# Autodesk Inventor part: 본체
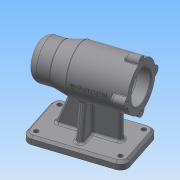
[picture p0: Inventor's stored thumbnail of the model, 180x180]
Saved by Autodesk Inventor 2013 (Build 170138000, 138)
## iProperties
Created: 2019-07
Part Number: 본체
Material: 알루미늄 6061
Document SubType Name: Modeling
Designer: Administrator
Density: 2.71 g/cm^3
Mass: 645.344 g
Surface Area: 653.867 cm^2
Volume: 238.134 cm^3
Author: Administrator
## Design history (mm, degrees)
sketch "스케치1"
  geometry: L1 (-56, 35)-(56, 35); L2 (56, 35)-(56, -35); L3 (56, -35)-(-56, -35); L4 (-56, -35)-(-56, 35); L5 (-56, 35)-(56, -35); L6 (56, 35)-(-56, -35); 1 further point
  constraints: 12 end point, 2 midpoint, 2 parallel, 1 horizontal, 1 perpendicular
  dimensions: "d0" = 112 distance of L2.end L3.end; "d1" = 70 distance of L1.end L2.end
extrude "돌출1" new body sketch "스케치1" distance "d2" = 10; taper "d3" = 0 deg
sketch "스케치2"
  geometry: L1 (-56, 80)-(-56, 105); L2 (-56, 105)-(-31, 105); L3 (-31, 105)-(-11, 110); L4 (-11, 110)-(56, 110); L5 (56, 110)-(56, 80); L6 (56, 80)-(-56, 80); L7 (-56, 0)-(56, 0) reference; 3 further points
  constraints: 12 end point, 3 parallel, 2 midpoint, 1 perpendicular, 1 vertical, 1 vertical alignment
  dimensions: "d4" = 50 diameter of L2 L6; "d6" = 60 diameter of L4 L6; "d7" = 112 distance of L5.end L1.start; "d8" = 80 distance between parallel lines of L7 L6; "d9" = 25 distance of L1.end L2.end; "d10" = 45 distance from line of L3.end L1
revolve "회전1" sketch "스케치2" stored, may be unused: angle "d11" = 90 deg
sketch "스케치3"
  geometry: L1 (56, 50)-(56, 110) reference; L2 (-56, 55)-(-56, 105) reference; L3 (56, 80)-(-56, 80); L4 (56, 101)-(41, 101); L5 (41, 101)-(41, 104); L6 (41, 104)-(-13, 104); L7 (-13, 104)-(-13, 101); L8 (-13, 101)-(-25, 101); L9 (-25, 101)-(-25, 97.5); L10 (-25, 97.5)-(-43, 97.5); L11 (-43, 97.5)-(-43, 96); L12 (-43, 96)-(-47, 96); L13 (56, 101)-(56, 80); L14 (-47, 90.5)-(-50, 90.5); L15 (-50, 90.5)-(-50, 80); L16 (-47, 96)-(-47, 90.5); 2 further points
  constraints: 28 end point, 8 parallel, 3 midpoint, 3 perpendicular, 2 collinear, 1 point on line, 1 vertical alignment
  dimensions: "d12" = 15 distance of L4.start L4.end; "d14" = 54 distance of L5.end L6.end; "d15" = 12 distance of L7.end L8.end; "d16" = 18 distance of L9.end L10.end; "d17" = 4 distance of L11.end L12.end; "d18" = 3 distance of L14.start L14.end; "d19" = 42 diameter of L4 L3; "d20" = 48 diameter of L6 L3; "d21" = 21 diameter of L14 L3; "d22" = 32 diameter of L12 L3; "d23" = 35 diameter of L10 L3; "d24" = 42 diameter of L8 L3
revolve "회전2" sketch "스케치3" stored, may be unused: angle "d25" = 90 deg
sketch "스케치4"
  geometry: L1 (56, -35)-(56, 35) reference; L2 (-36, 4)-(36, 4); L3 (36, 4)-(36, -4); L4 (36, -4)-(-36, -4); L5 (-36, -4)-(-36, 4); 3 further points
  constraints: 8 end point, 2 midpoint, 2 parallel, 1 horizontal, 1 horizontal alignment, 1 perpendicular, 1 vertical alignment
  dimensions: "d29" = 8 distance of L4.end L2.start; "d31" = 20 distance between parallel lines of L1 L3
extrude "돌출2" join sketch "스케치4" stored distance "d33" = 10; taper "d34" = 0 deg
feature "면 기울기1" dims angle "d35" = 20 deg
sketch "스케치6"
  geometry: C1 r 21 at (0, 0) reference; C2 r 6 at (0, 30); 1 further point
  constraints: 1 centre point, 1 vertical alignment
  dimensions: "d44" = 12 diameter of C2; "d45" = 30 distance of C2.centre C1.centre
extrude "돌출4" join sketch "스케치6" distance "d46" = 16; taper "d47" = 0 deg
sketch "스케치7"
  geometry: A1 r 6 centre (0, 0) between (5.97, -0.6) and (-5.97, -0.6) reference; 2 further points
  constraints: 1 coincident
hole "구멍1" sketch "스케치7" at (0, 0) diameter "d48" = 3.459; stored, may be unused: countersink angle "d52" = 90 deg, drill point angle "d54" = 118 deg; dims "d49" = 8, "d50" = 4, "d51" = 2, "d53" = 11
fillet "모깎기1" dims "d58" = 10
sketch "스케치8"
  geometry: A1 r 10 centre (46, -25) between (46, -35) and (56, -25) reference; A2 r 10 centre (46, 25) between (56, 25) and (46, 35) reference; A3 r 10 centre (-46, 25) between (-46, 35) and (-56, 25) reference; A4 r 10 centre (-46, -25) between (-56, -25) and (-46, -35) reference; 5 further points
  constraints: 4 coincident
hole "구멍2" sketch "스케치8" at (-46, 25), (-46, -25), (46, 25), (46, -25) diameter "d59" = 6; stored, may be unused: countersink angle "d63" = 90 deg, drill point angle "d65" = 0 deg; dims "d60" = 8, "d61" = 4, "d62" = 2, "d64" = 11
chamfer "모따기1" distance "d66" = 3; stored, may be unused: second distance "d67" = 2, angle "d68" = 45 deg
fillet "모깎기8" dims "d75" = 10
fillet "모깎기9" dims "d76" = 3
sketch "스케치9"
  geometry: L1 (-46, 32)-(46, 32) reference; L2 (46, -32)-(-46, -32) reference; L3 (-4, 25)-(4, 25); L4 (4, 25)-(4, -25); L5 (4, -25)-(-4, -25); L6 (-4, -25)-(-4, 25); 2 further points
  constraints: 8 end point, 2 parallel, 1 horizontal, 1 midpoint, 1 perpendicular, 1 vertical alignment
  dimensions: "d77" = 8 distance of L3.start L3.end; "d79" = 7 distance between parallel lines of L1 L3; "d80" = 7 distance between parallel lines of L2 L5
extrude "돌출5" join sketch "스케치9" stored distance "d81" = 16; taper "d82" = 0 deg
feature "면 기울기4" dims angle "d83" = 10 deg
fillet "모깎기10" dims "d84" = 3
fillet "모깎기11" dims "d85" = 3
fillet "모깎기12" dims "d86" = 3
fillet "모깎기13" dims "d87" = 3
chamfer "모따기2" distance "d88" = 1; stored, may be unused: second distance "d89" = 2, angle "d90" = 45 deg
fillet "모깎기14" dims "d91" = 0.3
fillet "모깎기15" dims "d96" = 3
fillet "모깎기16" dims "d97" = 1
node "작업 평면2"
sketch "스케치11"
  geometry: L1 (33.5, 36)-(33.5, 30.171) reference; L2 (-33.131, 30)-(16.5, 30) reference; 2 further points
  constraints: 1 other
  dimensions: "d98" = 42 distance from line of point (-8.5, 0) L1; "d99" = 30 distance from line of point (-8.5, 0) L2
feature "엠보싱2" sketch "스케치11" dims "d0" = 112, "d1" = 70, "d100" = 0.5, "d101" = 0
node "솔리드1"
pattern_circular "원형 패턴1" dims angle "d56" = 360 deg
